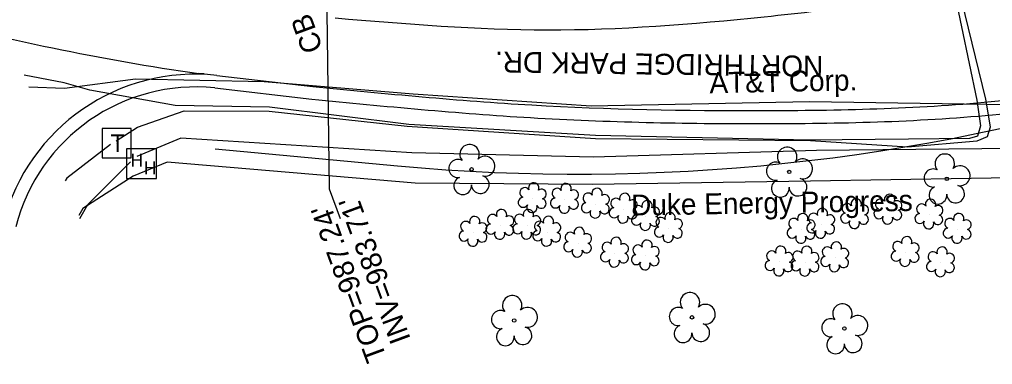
# Model space of a CAD drawing. Extents: x 1614427 to 1617186, y 896524 to 905462.
# Drawn here: x 1615875.6 to 1616061.5, y 903962.7 to 904028.5 of the extents above; entities that cross this region are included whole.
import ezdxf

# ---------------------------------------------------------------- set-up
doc = ezdxf.new("R2010")
doc.units = 0
for name, color, linetype in [('Exist Right of Way Line', 7, 'Continuous'), ('Exist Roads Curbs', 7, 'Continuous'), ('Exist Roads EOP', 7, 'Continuous'), ('Exist Roads EOP Text', 7, 'Continuous'), ('Exist Roads EOT', 7, 'Continuous'), ('Exist Structure Minor Catch Basin Leader', 7, 'Continuous'), ('Exist Structure Minor Catch Basin Text', 7, 'Continuous'), ('Exist Structure Minor Catch Basin Top Elevation', 7, 'Continuous'), ('Exist Structure Minor Pipes RCP 15 Inch Invert', 7, 'Continuous'), ('Exist Utilities Power UG Cable SUE LOS B', 7, 'Continuous'), ('Exist Utilities Power UG Cable SUE LOS B Text', 7, 'Continuous'), ('Exist Utilities Telephone Hand Hole CELL', 7, 'Continuous'), ('Exist Utilities Telephone Pedestal CELL', 7, 'Continuous'), ('Exist Utilities Telephone UG Cable SUE LOS B', 7, 'Continuous'), ('Exist Utilities Telephone UG FO SUE LOS B', 7, 'Continuous'), ('Exist Utilities Telephone UG FO SUE LOS B Text', 7, 'Continuous'), ('Exist Vegetation Shrub CELL', 7, 'Continuous'), ('Exist Vegetation Tree CELL', 7, 'Continuous')]:
    doc.layers.add(name, color=color, linetype=linetype)

# ---------------------------------------------------------------- blocks, each defined once
blk = doc.blocks.new('EXIST UTILITIES TELEPHONE PEDESTAL')
at = {"layer": 'Exist Utilities Telephone Pedestal CELL'}
blk.add_line((0, 0), (0, 0), dxfattribs=at)
blk.add_lwpolyline([(-0.0545, -0.0565), (0.0574, -0.0565), (0.0574, 0.0554), (-0.0545, 0.0554), (-0.0545, -0.0565)], dxfattribs=at)
blk.add_text('T', height=0.0684, dxfattribs=at).set_placement((-0.0226, -0.0343))

msp = doc.modelspace()

# ---------------------------------------------------------------- linework, layer by layer
at = {"layer": 'Exist Right of Way Line'}
msp.add_line((1615912.95, 904003.79), (1615947.78, 904000.58), dxfattribs=at)
msp.add_arc((1615982.39, 904376.05), 377.06, 264.7333, 287.2667, dxfattribs=at)
at = {"layer": 'Exist Roads Curbs'}
msp.add_line((1615912.91, 904015.44), (1615931.47, 904013.3), dxfattribs=at)
msp.add_ellipse((1615909.32, 903979.99), major_axis=(15.46, -32.12), ratio=0.998343, start_param=2.591326, end_param=4.009692, dxfattribs=at)
msp.add_spline([(1615931.47, 904013.3), (1615973.24, 904009.77), (1616017.42, 904008.63), (1616061.47, 904010.33), (1616104.95, 904016.64)], degree=3, dxfattribs=at)
at = {"layer": 'Exist Roads EOP'}
msp.add_line((1615913.28, 904017.82), (1615931.62, 904015.71), dxfattribs=at)
msp.add_ellipse((1615909.15, 903980.17), major_axis=(-19.18, 32.68), ratio=0.998661, start_param=5.642651, end_param=7.067278, dxfattribs=at)
for points in [[(1616097.99, 904045.33), (1616058.52, 904034.87), (1616017.88, 904028.96), (1615976.43, 904026.45), (1615935.89, 904028.72)], [(1615931.62, 904015.71), (1615973.45, 904012.19), (1616017.45, 904011.12), (1616061.25, 904012.84), (1616104.38, 904019.1)]]:
    msp.add_spline(points, degree=3, dxfattribs=at)
at = {"layer": 'Exist Roads EOT'}
msp.add_line((1615910.9, 904018.1), (1615909.86, 904018.2), dxfattribs=at)
msp.add_ellipse((1615972.71, 904454.31), major_axis=(399.48, 187.91), ratio=0.997263, start_param=4.002237, end_param=4.130845, dxfattribs=at)
at = {"layer": 'Exist Structure Minor Catch Basin Leader'}
msp.add_lwpolyline([(1615934.33, 904029.89), (1615934.75, 903996.19), (1615936.83, 903990.56)], dxfattribs=at)
at = {"layer": 'Exist Utilities Power UG Cable SUE LOS B'}
msp.add_lwpolyline([(1616175.37, 903932.73), (1616162.82, 903955.92), (1616154.05, 903981.84), (1616149.33, 903992.61), (1616140.12, 904002.5), (1616134.79, 904005.2), (1616125.79, 904006.53), (1616114.47, 904005.33), (1616072.77, 903998.44), (1616026.71, 903997.66), (1615985.03, 903997.01), (1615951.2, 903997.28), (1615903.82, 904001.29), (1615897.29, 903998.6), (1615887.7, 903992.46), (1615886.9, 903991.11)], dxfattribs=at)
at = {"layer": 'Exist Utilities Telephone Hand Hole CELL'}
for p, q in [((1615896.01, 904003.85), (1615896.01, 903998.13)), ((1615901.74, 904003.85), (1615896.01, 904003.85)), ((1615901.74, 903998.13), (1615901.74, 904003.85)), ((1615898.87, 904000.99), (1615898.87, 904000.99)), ((1615896.01, 903998.13), (1615901.74, 903998.13))]:
    msp.add_line(p, q, dxfattribs=at)
at = {"layer": 'Exist Utilities Telephone UG Cable SUE LOS B'}
for points in [[(1616051.18, 904048.12), (1616058.49, 904013.1), (1616059.21, 904008.2), (1616058.59, 904006.25), (1616057.07, 904005.82), (1616045.43, 904005.69), (1616026.41, 904005.5), (1615985.6, 904006.34), (1615949.97, 904008.48), (1615923.34, 904011.77), (1615905.33, 904012.06), (1615889.01, 904015.04), (1615884.15, 904016.41), (1615876.48, 904017.85)], [(1615894.08, 904005.35), (1615898.16, 904007.95), (1615907.05, 904011.06), (1615923.29, 904011.03), (1615949.68, 904008.12), (1615985.61, 904005.82), (1616026.69, 904005.38), (1616045.24, 904004.22), (1616058.54, 904005.35), (1616060.53, 904006.18), (1616061.09, 904008), (1616060.18, 904013.3), (1616051.64, 904048.27)], [(1615892.98, 904004.62), (1615884.66, 903998.23), (1615884.34, 903997.7)]]:
    msp.add_lwpolyline(points, dxfattribs=at)
at = {"layer": 'Exist Utilities Telephone UG FO SUE LOS B'}
for points in [[(1616249.11, 903962.1), (1616244.79, 903961.17), (1616238.35, 903961.16), (1616200.69, 903950.89), (1616195.93, 903950.49), (1616193.23, 903952.67), (1616190.15, 903959.25), (1616186.96, 903970.12), (1616182.94, 903976.59), (1616168.24, 903986.65), (1616161.85, 903994.6), (1616153.95, 904004.6), (1616148.06, 904010.09), (1616140.82, 904013.46), (1616124.88, 904014.78), (1616105.51, 904016.53), (1616064.53, 904012.24), (1616026.51, 904012.8), (1615984.81, 904011.98), (1615950.8, 904014.23), (1615922.36, 904016.58), (1615897.75, 904017.11), (1615884.16, 904015.33), (1615877.39, 904015.58)], [(1616231.95, 903831.99), (1616208.49, 903896.38), (1616196.66, 903929.39), (1616185.98, 903956.69), (1616178.38, 903970.82), (1616170.63, 903982.39), (1616159.03, 903993.51), (1616152.27, 904000.63), (1616146.16, 904003.93), (1616135.11, 904008.46), (1616113.93, 904008.67), (1616072.1, 904003.93), (1616027.82, 904003.5), (1615985.23, 904002.2), (1615950.55, 904003.04), (1615906.43, 904005.88), (1615898.01, 904002.34)], [(1615887.12, 903990.53), (1615888.62, 903993.17), (1615896.78, 904001.37)]]:
    msp.add_lwpolyline(points, dxfattribs=at)
at = {"layer": 'Exist Vegetation Shrub CELL'}
for p, q in [((1615973.62, 903994.33), (1615973.62, 903994.33)), ((1615979.78, 903994.19), (1615979.78, 903994.19)), ((1615985.7, 903993.29), (1615985.7, 903993.29)), ((1615991, 903992.32), (1615991, 903992.32)), ((1616041.58, 903992.14), (1616041.58, 903992.14)), ((1615995.26, 903990.93), (1615995.26, 903990.93)), ((1616035.21, 903991.28), (1616035.21, 903991.28)), ((1616049.41, 903991.22), (1616049.41, 903991.22)), ((1615967.45, 903989.23), (1615967.45, 903989.23)), ((1615972.57, 903989.25), (1615972.57, 903989.25)), ((1615999.63, 903988.64), (1615999.63, 903988.64)), ((1616024.98, 903988.46), (1616024.98, 903988.46)), ((1616028.74, 903989.44), (1616028.74, 903989.44)), ((1616054.81, 903988.47), (1616054.81, 903988.47)), ((1615962.31, 903987.9), (1615962.31, 903987.9)), ((1615976.4, 903987.92), (1615976.4, 903987.92)), ((1615982.3, 903985.83), (1615982.3, 903985.83)), ((1615989.35, 903983.92), (1615989.35, 903983.92)), ((1615995.23, 903983.38), (1615995.23, 903983.38)), ((1616031.4, 903983.03), (1616031.4, 903983.03)), ((1616044.88, 903984.06), (1616044.88, 903984.06)), ((1616020.78, 903982.25), (1616020.78, 903982.25)), ((1616025.74, 903982.23), (1616025.74, 903982.23)), ((1616051.62, 903982.09), (1616051.62, 903982.09))]:
    msp.add_line(p, q, dxfattribs=at)
for centre, radius, start, end in [((1615973.85, 903996.37), 0.99, 334.8391, 200.4717), ((1615972.14, 903995.46), 0.968, 35.8908, 245.4216), ((1615975.3, 903995.2), 0.929, 284.4567, 126.0861), ((1615978.3, 903995.32), 0.968, 35.8908, 245.4216), ((1615980.01, 903996.23), 0.99, 334.8391, 200.4717), ((1615981.45, 903995.06), 0.929, 284.4567, 126.0861), ((1615984.21, 903994.42), 0.968, 35.8908, 245.4216), ((1615985.93, 903995.33), 0.99, 334.8391, 200.4717), ((1615971.82, 903993.62), 0.955, 95.1099, 327.9534), ((1615975.26, 903993.4), 0.937, 204.9913, 73.4601), ((1615977.98, 903993.49), 0.955, 95.1099, 327.9534), ((1615981.42, 903993.26), 0.937, 204.9913, 73.4601), ((1615983.9, 903992.58), 0.955, 95.1099, 327.9534), ((1615987.37, 903994.16), 0.929, 284.4567, 126.0861), ((1615989.51, 903993.44), 0.968, 35.8908, 245.4216), ((1615991.23, 903994.36), 0.99, 334.8391, 200.4717), ((1615992.67, 903993.18), 0.929, 284.4567, 126.0861), ((1615995.49, 903992.97), 0.99, 334.8391, 200.4717), ((1616035.44, 903993.32), 0.99, 334.8391, 200.4717), ((1616040.09, 903993.26), 0.968, 35.8908, 245.4216), ((1616041.81, 903994.18), 0.99, 334.8391, 200.4717), ((1616043.25, 903993), 0.929, 284.4567, 126.0861), ((1616049.64, 903993.26), 0.99, 334.8391, 200.4717), ((1615967.68, 903991.27), 0.99, 334.8391, 200.4717), ((1615972.8, 903991.29), 0.99, 334.8391, 200.4717), ((1615973.5, 903992.65), 0.984, 151.2797, 21.387), ((1615979.65, 903992.51), 0.984, 151.2797, 21.387), ((1615985.57, 903991.6), 0.984, 151.2797, 21.387), ((1615987.33, 903992.36), 0.937, 204.9913, 73.4601), ((1615989.2, 903991.61), 0.955, 95.1099, 327.9534), ((1615992.63, 903991.39), 0.937, 204.9913, 73.4601), ((1615993.78, 903992.06), 0.968, 35.8908, 245.4216), ((1615996.93, 903991.8), 0.929, 284.4567, 126.0861), ((1615999.86, 903990.68), 0.99, 334.8391, 200.4717), ((1616028.97, 903991.48), 0.99, 334.8391, 200.4717), ((1616033.72, 903992.41), 0.968, 35.8908, 245.4216), ((1616036.88, 903992.15), 0.929, 284.4567, 126.0861), ((1616039.78, 903991.43), 0.955, 95.1099, 327.9534), ((1616043.21, 903991.21), 0.937, 204.9913, 73.4601), ((1616047.93, 903992.35), 0.968, 35.8908, 245.4216), ((1616051.09, 903992.09), 0.929, 284.4567, 126.0861), ((1615960.83, 903989.02), 0.968, 35.8908, 245.4216), ((1615962.54, 903989.94), 0.99, 334.8391, 200.4717), ((1615965.97, 903990.35), 0.968, 35.8908, 245.4216), ((1615969.12, 903990.1), 0.929, 284.4567, 126.0861), ((1615971.09, 903990.38), 0.968, 35.8908, 245.4216), ((1615974.24, 903990.12), 0.929, 284.4567, 126.0861), ((1615974.92, 903989.05), 0.968, 35.8908, 245.4216), ((1615976.63, 903989.96), 0.99, 334.8391, 200.4717), ((1615990.87, 903990.63), 0.984, 151.2797, 21.387), ((1615993.46, 903990.23), 0.955, 95.1099, 327.9534), ((1615996.9, 903990), 0.937, 204.9913, 73.4601), ((1615998.15, 903989.77), 0.968, 35.8908, 245.4216), ((1616001.31, 903989.51), 0.929, 284.4567, 126.0861), ((1616023.5, 903989.59), 0.968, 35.8908, 245.4216), ((1616025.21, 903990.5), 0.99, 334.8391, 200.4717), ((1616026.66, 903989.33), 0.929, 284.4567, 126.0861), ((1616027.26, 903990.57), 0.968, 35.8908, 245.4216), ((1616030.41, 903990.31), 0.929, 284.4567, 126.0861), ((1616033.41, 903990.58), 0.955, 95.1099, 327.9534), ((1616035.08, 903989.6), 0.984, 151.2797, 21.387), ((1616036.84, 903990.35), 0.937, 204.9913, 73.4601), ((1616041.45, 903990.45), 0.984, 151.2797, 21.387), ((1616047.61, 903990.52), 0.955, 95.1099, 327.9534), ((1616049.29, 903989.54), 0.984, 151.2797, 21.387), ((1616051.05, 903990.29), 0.937, 204.9913, 73.4601), ((1616053.33, 903989.59), 0.968, 35.8908, 245.4216), ((1616055.04, 903990.51), 0.99, 334.8391, 200.4717), ((1616056.48, 903989.34), 0.929, 284.4567, 126.0861), ((1615960.51, 903987.19), 0.955, 95.1099, 327.9534), ((1615963.98, 903988.77), 0.929, 284.4567, 126.0861), ((1615965.65, 903988.52), 0.955, 95.1099, 327.9534), ((1615967.32, 903987.54), 0.984, 151.2797, 21.387), ((1615969.09, 903988.3), 0.937, 204.9913, 73.4601), ((1615970.77, 903988.55), 0.955, 95.1099, 327.9534), ((1615972.44, 903987.57), 0.984, 151.2797, 21.387), ((1615974.21, 903988.32), 0.937, 204.9913, 73.4601), ((1615974.6, 903987.22), 0.955, 95.1099, 327.9534), ((1615978.07, 903988.79), 0.929, 284.4567, 126.0861), ((1615982.52, 903987.87), 0.99, 334.8391, 200.4717), ((1615995.13, 903989.25), 0.984, 151.2797, 21.387), ((1615997.83, 903987.94), 0.955, 95.1099, 327.9534), ((1616001.27, 903987.71), 0.937, 204.9913, 73.4601), ((1616023.18, 903987.76), 0.955, 95.1099, 327.9534), ((1616026.62, 903987.53), 0.937, 204.9913, 73.4601), ((1616026.94, 903988.73), 0.955, 95.1099, 327.9534), ((1616028.61, 903987.76), 0.984, 151.2797, 21.387), ((1616030.38, 903988.51), 0.937, 204.9913, 73.4601), ((1616053.01, 903987.76), 0.955, 95.1099, 327.9534), ((1616056.45, 903987.54), 0.937, 204.9913, 73.4601), ((1615962.18, 903986.21), 0.984, 151.2797, 21.387), ((1615963.95, 903986.97), 0.937, 204.9913, 73.4601), ((1615976.27, 903986.24), 0.984, 151.2797, 21.387), ((1615978.04, 903986.99), 0.937, 204.9913, 73.4601), ((1615980.5, 903985.13), 0.955, 95.1099, 327.9534), ((1615980.81, 903986.96), 0.968, 35.8908, 245.4216), ((1615983.97, 903986.7), 0.929, 284.4567, 126.0861), ((1615989.58, 903985.96), 0.99, 334.8391, 200.4717), ((1615995.46, 903985.42), 0.99, 334.8391, 200.4717), ((1615999.5, 903986.96), 0.984, 151.2797, 21.387), ((1616024.86, 903986.78), 0.984, 151.2797, 21.387), ((1616043.4, 903985.19), 0.968, 35.8908, 245.4216), ((1616045.11, 903986.1), 0.99, 334.8391, 200.4717), ((1616054.68, 903986.78), 0.984, 151.2797, 21.387), ((1615982.17, 903984.15), 0.984, 151.2797, 21.387), ((1615983.93, 903984.9), 0.937, 204.9913, 73.4601), ((1615987.87, 903985.05), 0.968, 35.8908, 245.4216), ((1615991.02, 903984.79), 0.929, 284.4567, 126.0861), ((1615993.74, 903984.51), 0.968, 35.8908, 245.4216), ((1615996.9, 903984.25), 0.929, 284.4567, 126.0861), ((1616019.29, 903983.38), 0.968, 35.8908, 245.4216), ((1616021.01, 903984.29), 0.99, 334.8391, 200.4717), ((1616024.26, 903983.35), 0.968, 35.8908, 245.4216), ((1616025.97, 903984.27), 0.99, 334.8391, 200.4717), ((1616029.92, 903984.16), 0.968, 35.8908, 245.4216), ((1616031.63, 903985.07), 0.99, 334.8391, 200.4717), ((1616033.08, 903983.9), 0.929, 284.4567, 126.0861), ((1616043.08, 903983.35), 0.955, 95.1099, 327.9534), ((1616046.55, 903984.93), 0.929, 284.4567, 126.0861), ((1616051.85, 903984.13), 0.99, 334.8391, 200.4717), ((1615987.55, 903983.22), 0.955, 95.1099, 327.9534), ((1615989.22, 903982.24), 0.984, 151.2797, 21.387), ((1615990.99, 903982.99), 0.937, 204.9913, 73.4601), ((1615993.43, 903982.68), 0.955, 95.1099, 327.9534), ((1615996.86, 903982.46), 0.937, 204.9913, 73.4601), ((1616018.98, 903981.55), 0.955, 95.1099, 327.9534), ((1616022.45, 903983.12), 0.929, 284.4567, 126.0861), ((1616023.94, 903981.52), 0.955, 95.1099, 327.9534), ((1616027.41, 903983.1), 0.929, 284.4567, 126.0861), ((1616029.6, 903982.32), 0.955, 95.1099, 327.9534), ((1616033.04, 903982.1), 0.937, 204.9913, 73.4601), ((1616044.75, 903982.38), 0.984, 151.2797, 21.387), ((1616046.52, 903983.13), 0.937, 204.9913, 73.4601), ((1616050.13, 903983.22), 0.968, 35.8908, 245.4216), ((1616053.29, 903982.96), 0.929, 284.4567, 126.0861), ((1615995.1, 903981.7), 0.984, 151.2797, 21.387), ((1616020.65, 903980.57), 0.984, 151.2797, 21.387), ((1616022.41, 903981.32), 0.937, 204.9913, 73.4601), ((1616025.61, 903980.54), 0.984, 151.2797, 21.387), ((1616027.38, 903981.3), 0.937, 204.9913, 73.4601), ((1616031.28, 903981.35), 0.984, 151.2797, 21.387), ((1616049.82, 903981.39), 0.955, 95.1099, 327.9534), ((1616051.49, 903980.41), 0.984, 151.2797, 21.387), ((1616053.25, 903981.16), 0.937, 204.9913, 73.4601)]:
    msp.add_arc(centre, radius, start, end, dxfattribs=at)
at = {"layer": 'Exist Vegetation Tree CELL'}
for p, q in [((1615961.96, 903999.91), (1615961.96, 903999.91)), ((1616022.64, 903999.41), (1616022.64, 903999.41)), ((1616052.75, 903998.1), (1616052.75, 903998.1)), ((1616004.07, 903971.67), (1616004.07, 903971.67)), ((1615970.1, 903971.08), (1615970.1, 903971.08)), ((1616033.19, 903969.54), (1616033.19, 903969.54))]:
    msp.add_line(p, q, dxfattribs=at)
for centre in [(1615961.96, 903999.91), (1616022.64, 903999.41), (1616052.75, 903998.1), (1615970.1, 903971.08), (1616004.07, 903971.67), (1616033.19, 903969.54)]:
    msp.add_circle(centre, 0.326, dxfattribs=at)
for centre, radius, start, end in [((1615961.57, 904002.79), 1.86, 330.1651, 219.7134), ((1616022.25, 904002.29), 1.86, 330.1651, 219.7134), ((1616052.36, 904000.98), 1.86, 330.1651, 219.7134), ((1615959.35, 904000.07), 1.73, 62.6636, 279.3457), ((1615964.51, 904000.5), 1.9, 257.1011, 134.1999), ((1616020.03, 903999.57), 1.73, 62.6636, 279.3457), ((1616025.19, 904000), 1.9, 257.1011, 134.1999), ((1616050.14, 903998.26), 1.73, 62.6636, 279.3457), ((1616055.3, 903998.69), 1.9, 257.1011, 134.1999), ((1615960.26, 903996.79), 1.69, 111.5671, 6.231), ((1615963.63, 903997.02), 1.7, 181.2822, 74.56), ((1616020.93, 903996.29), 1.69, 111.5671, 6.231), ((1616024.31, 903996.52), 1.7, 181.2822, 74.56), ((1616051.04, 903994.98), 1.69, 111.5671, 6.231), ((1616054.42, 903995.2), 1.7, 181.2822, 74.56), ((1615969.72, 903973.96), 1.86, 330.1651, 219.7134), ((1616003.68, 903974.54), 1.86, 330.1651, 219.7134), ((1615972.65, 903971.67), 1.9, 257.1011, 134.1999), ((1616001.46, 903971.82), 1.73, 62.6636, 279.3457), ((1616006.62, 903972.26), 1.9, 257.1011, 134.1999), ((1616032.8, 903972.41), 1.86, 330.1651, 219.7134), ((1615967.5, 903971.24), 1.73, 62.6636, 279.3457), ((1616030.58, 903969.69), 1.73, 62.6636, 279.3457), ((1616035.74, 903970.13), 1.9, 257.1011, 134.1999), ((1615968.4, 903967.96), 1.69, 111.5671, 6.231), ((1615971.77, 903968.18), 1.7, 181.2822, 74.56), ((1616002.36, 903968.55), 1.69, 111.5671, 6.231), ((1616005.74, 903968.77), 1.7, 181.2822, 74.56), ((1616031.49, 903966.42), 1.69, 111.5671, 6.231), ((1616034.86, 903966.64), 1.7, 181.2822, 74.56)]:
    msp.add_arc(centre, radius, start, end, dxfattribs=at)

# ---------------------------------------------------------------- block references
at = {"layer": 'Exist Utilities Telephone Pedestal CELL', "xscale": 50, "yscale": 50}
msp.add_blockref('EXIST UTILITIES TELEPHONE PEDESTAL', (1615894.08, 904004.91), dxfattribs=at)

# ---------------------------------------------------------------- texts
at = {"layer": 'Exist Roads EOP Text'}
msp.add_text('NORTHRIDGE PARK DR.', height=4, rotation=179.239, dxfattribs=at).set_placement((1616029.16, 904021.55))
at = {"layer": 'Exist Structure Minor Catch Basin Text'}
msp.add_text('CB', height=4, rotation=110.2165, dxfattribs=at).set_placement((1615933.62, 904022.95))
at = {"layer": 'Exist Structure Minor Catch Basin Top Elevation'}
msp.add_text("TOP=987.24'", height=4, rotation=110.2165, dxfattribs=at).set_placement((1615945.79, 903964.02))
at = {"layer": 'Exist Structure Minor Pipes RCP 15 Inch Invert'}
msp.add_text("INV=983.71'", height=4, rotation=110.2165, dxfattribs=at).set_placement((1615950.37, 903967.54))
at = {"layer": 'Exist Utilities Power UG Cable SUE LOS B Text'}
msp.add_text('Duke Energy Progress', height=4, rotation=0.9677, dxfattribs=at).set_placement((1615992.46, 903991.08))
at = {"layer": 'Exist Utilities Telephone Hand Hole CELL'}
for p in [(1615896.79, 904000.4), (1615899.36, 903998.93)]:
    msp.add_text('H', height=2.5, dxfattribs=at).set_placement(p)
at = {"layer": 'Exist Utilities Telephone UG FO SUE LOS B Text'}
msp.add_text('AT&T Corp.', height=4, rotation=1.1182, dxfattribs=at).set_placement((1616007.44, 904014.42))

doc.saveas('drawing.dxf')
